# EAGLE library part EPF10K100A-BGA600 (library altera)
EPF10K100 FLEX 10K family
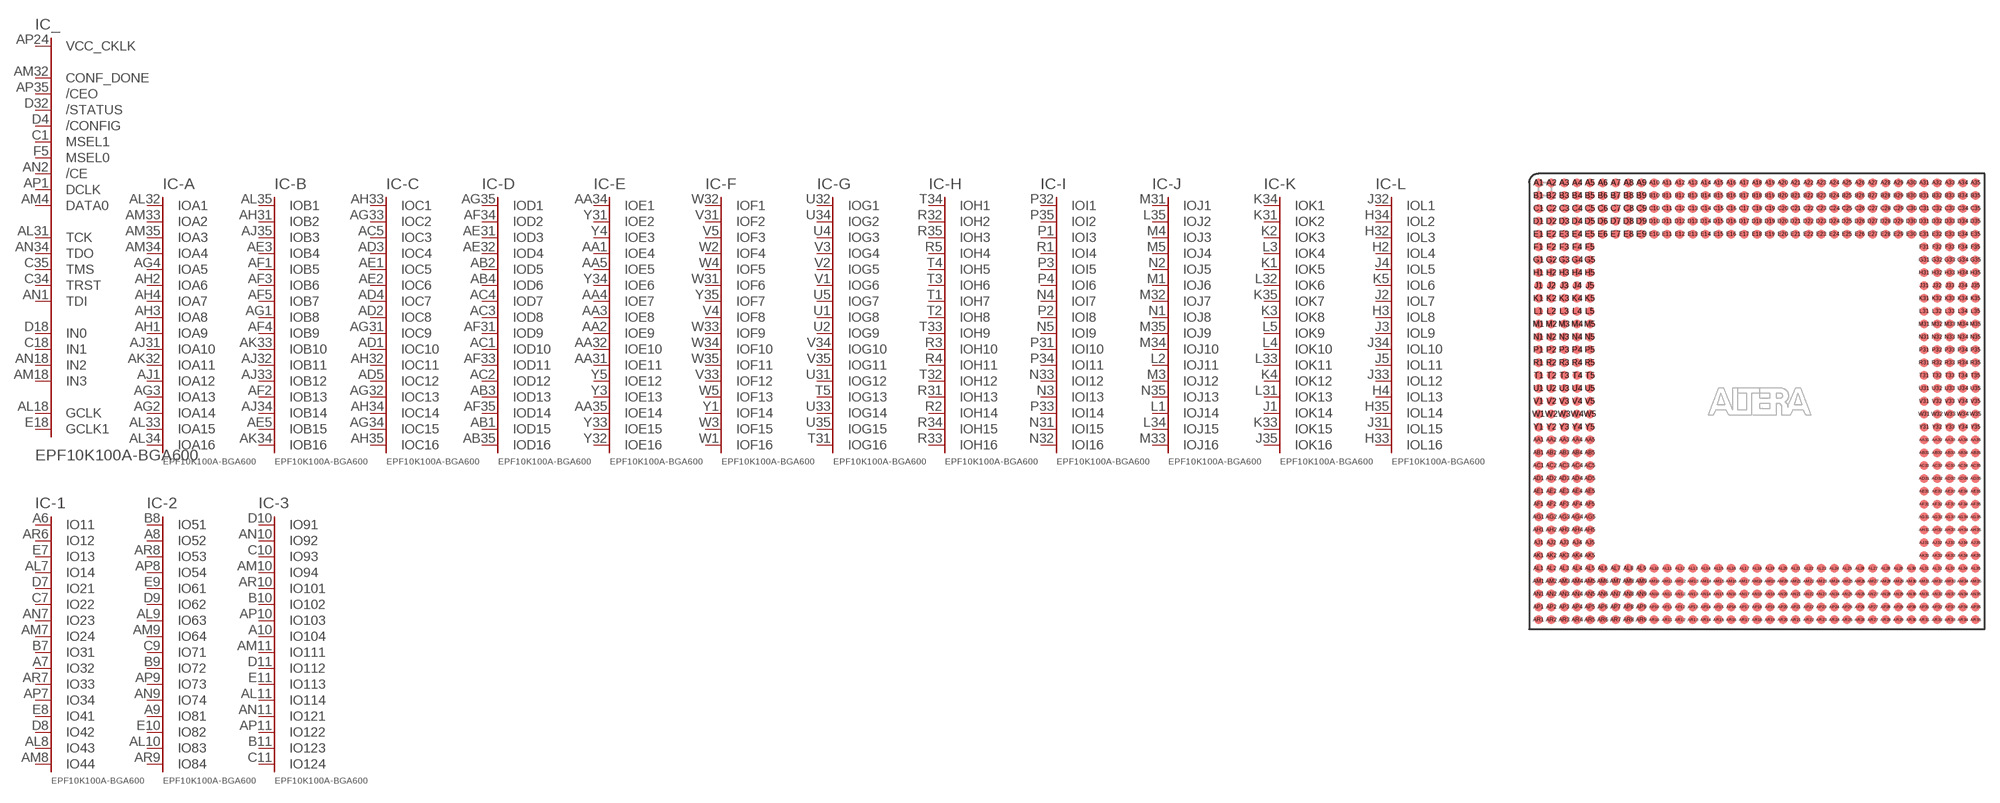
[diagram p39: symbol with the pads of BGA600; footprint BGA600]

Designator prefix IC; gates _=100B600C -A=A16 -B=B16 -C=C16 -D=D16 -E=E16 -F=F16 -G=G16 -H=H16 -I=I16 -J=J16 -K=K16 -L=L16 -1=IO44 -2=IO84 -3=IO124 -4=IO164 -5=IO204 -6=IO244 -7=IO284 -8=IO324 -9=IO364 -10=IO404 -11=IO444 -12=IO484 -13=IO524 G1=GND G2=GND G3=GND G4=GND G5=GND G6=GND G7=GND G8=GND G9=GND G10=GND G11=GND G12=GND G13=GND G14=GND G15=GND G16=GND G17=GND G18=GND G19=GND G20=GND G21=GND G22=GND G23=GND G24=GND G25=GND G26=GND G27=GND G28=GND G29=GND G30=GND G31=GND G32=GND G33=GND G34=GND G35=GND G36=GND G37=GND G38=GND G39=GND G40=GND G41=GND G42=GND G43=GND G44=GND G45=GND G46=GND G47=GND G48=GND G49=GND G50=GND G51=GND G52=GND G53=GND G54=GND G55=GND G56=GND G57=GND G58=GND NC1=NC NC2=NC NC3=NC NC4=NC NC5=NC NC6=NC NC7=NC NC8=NC NC9=NC NC10=NC NC11=NC NC12=NC NC13=NC NC14=NC NC15=NC NC16=NC NC17=NC NC18=NC NC19=NC NC20=NC NC21=NC NC22=NC NC23=NC NC24=NC NC25=NC NC26=NC NC27=NC NC28=NC NC29=NC NC30=NC NC31=NC NC32=NC NC33=NC NC34=NC NC35=NC NC36=NC NC37=NC NC38=NC NC39=NC NC40=NC NC41=NC NC42=NC NC43=NC NC44=NC NC45=NC NC46=NC NC47=NC NC48=NC NC49=NC NC50=NC NC51=NC NC52=NC NC53=NC NC54=NC NC55=NC NC56=NC NC57=NC NC58=NC NC59=NC NC60=NC NC61=NC NC62=NC NC63=NC NC64=NC V1=VCCINT V2=VCCINT V3=VCCINT V4=VCCINT V5=VCCINT V6=VCCINT V7=VCCINT V8=VCCINT V9=VCCINT V10=VCCINT V11=VCCINT V12=VCCINT V13=VCCINT V14=VCCINT V15=VCCINT V16=VCCINT V17=VCCINT V18=VCCINT V19=VCCINT V20=VCCINT V21=VCCINT V22=VCCINT V23=VCCINT V24=VCCINT V25=VCCINT V26=VCCINT V27=VCCINT V28=VCCINT VO1=VCCIO VO2=VCCIO VO3=VCCIO VO4=VCCIO VO5=VCCIO VO6=VCCIO VO7=VCCIO VO8=VCCIO VO9=VCCIO VO10=VCCIO VO11=VCCIO VO12=VCCIO VO13=VCCIO VO14=VCCIO VO15=VCCIO VO16=VCCIO VO17=VCCIO VO18=VCCIO VO19=VCCIO VO20=VCCIO VO21=VCCIO VO22=VCCIO VO23=VCCIO VO24=VCCIO VO25=VCCIO VO26=VCCIO VO27=VCCIO VO28=VCCIO VO29=VCCIO

## EPF10K100A-BGA600 (MPN: EPF10K100ABC600-1; OC_FARNELL: unknown; OC_NEWARK: 51R8783)  [BGA600]
A1  G30:GND  pwr
A2  G31:GND  pwr
A3  G32:GND  pwr
A4  G33:GND  pwr
A5  G34:GND  pwr
A6  -1:IO11
A7  -1:IO32
A8  -2:IO52
A9  -2:IO81
A10  -3:IO104
A11  V12:VCC  pwr
A12  -4:IO144
A13  -5:IO173
A14  -5:IO191
A15  -6:IO211
A16  -6:IO243
A17  -7:IO264
A18  G35:GND  pwr
A19  V13:VCC  pwr
A20  VO15:VCCIO  pwr
A21  -8:IO313
A22  -9:IO331
A23  -9:IO361
A24  -10:IO382
A25  -10:IO394
A26  -11:IO421
A27  VO16:VCCIO  pwr
A28  -12:IO472
A29  -13:IO492
A30  -13:IO523
A31  G36:GND  pwr
A32  G37:GND  pwr
A33  G38:GND  pwr
A34  G39:GND  pwr
A35  G40:GND  pwr
AA1  -E:IOE4
AA2  -E:IOE9
AA3  -E:IOE8
AA4  -E:IOE7
AA5  -E:IOE5
AA31  -E:IOE11
AA32  -E:IOE10
AA33  V1:VCC  pwr
AA34  -E:IOE1
AA35  -E:IOE14
AB1  -D:IOD15
AB2  -D:IOD5
AB3  -D:IOD13
AB4  -D:IOD6
AB5  V2:VCC  pwr
AB31  NC1:NC  nc
AB32  NC2:NC  nc
AB33  NC3:NC  nc
AB34  NC4:NC  nc
AB35  -D:IOD16
AC1  -D:IOD10
AC2  -D:IOD12
AC3  -D:IOD8
AC4  -D:IOD7
AC5  -C:IOC3
AC31  NC5:NC  nc
AC32  NC6:NC  nc
AC33  NC7:NC  nc
AC34  NC8:NC  nc
AC35  NC9:NC  nc
AD1  -C:IOC10
AD2  -C:IOC8
AD3  -C:IOC4
AD4  -C:IOC7
AD5  -C:IOC12
AD31  NC10:NC  nc
AD32  NC11:NC  nc
AD33  NC12:NC  nc
AD34  NC13:NC  nc
AD35  V3:VCC  pwr
AE1  -C:IOC5
AE2  -C:IOC6
AE3  -B:IOB4
AE4  V4:VCC  pwr
AE5  -B:IOB15
AE31  -D:IOD3
AE32  -D:IOD4
AE33  NC14:NC  nc
AE34  NC15:NC  nc
AE35  NC16:NC  nc
AF1  -B:IOB5
AF2  -B:IOB13
AF3  -B:IOB6
AF4  -B:IOB9
AF5  -B:IOB7
AF31  -D:IOD9
AF32  V5:VCC  pwr
AF33  -D:IOD11
AF34  -D:IOD2
AF35  -D:IOD14
AG1  -B:IOB8
AG2  -A:IOA14
AG3  -A:IOA13
AG4  -A:IOA5
AG5  V6:VCC  pwr
AG31  -C:IOC9
AG32  -C:IOC13
AG33  -C:IOC2
AG34  -C:IOC15
AG35  -D:IOD1
AH1  -A:IOA9
AH2  -A:IOA6
AH3  -A:IOA8
AH4  -A:IOA7
AH5  NC17:NC  nc
AH31  -B:IOB2
AH32  -C:IOC11
AH33  -C:IOC1
AH34  -C:IOC14
AH35  -C:IOC16
AJ1  -A:IOA12
AJ2  NC18:NC  nc
AJ3  NC19:NC  nc
AJ4  NC20:NC  nc
AJ5  NC21:NC  nc
AJ31  -A:IOA10
AJ32  -B:IOB11
AJ33  -B:IOB12
AJ34  -B:IOB14
AJ35  -B:IOB3
AK1  NC22:NC  nc
AK2  NC23:NC  nc
AK3  NC24:NC  nc
AK4  NC25:NC  nc
AK5  NC26:NC  nc
AK31  V7:VCC  pwr
AK32  -A:IOA11
AK33  -B:IOB10
AK34  -B:IOB16
AK35  V8:VCC  pwr
AL1  NC27:NC  nc
AL2  NC28:NC  nc
AL3  V9:VCC  pwr
AL4  NC29:NC  nc
AL5  VO1:VCCIO  pwr
AL6  G1:GND  pwr
AL7  -1:IO14
AL8  -1:IO43
AL9  -2:IO63
AL10  -2:IO83
AL11  -3:IO114
AL12  VO2:VCCIO  pwr
AL13  -4:IO154
AL14  -5:IO171
AL15  -5:IO204
AL16  -6:IO221
AL17  -6:IO242
AL18  _:GCLK  in
AL19  -8:IO292
AL20  -8:IO312
AL21  -9:IO343
AL22  -9:IO364
AL23  -10:IO381
AL24  -11:IO411
AL25  -11:IO434
AL26  -12:IO454
AL27  -12:IO471
AL28  -13:IO501
AL29  -13:IO522
AL30  G2:GND  pwr
AL31  _:TCK
AL32  -A:IOA1
AL33  -A:IOA15
AL34  -A:IOA16
AL35  -B:IOB1
AM1  NC30:NC  nc
AM2  NC31:NC  nc
AM3  NC32:NC  nc
AM4  _:DATA0  in
AM5  VO3:VCCIO  pwr
AM6  G3:GND  pwr
AM7  -1:IO24
AM8  -1:IO44
AM9  -2:IO64
AM10  -3:IO94
AM11  -3:IO111
AM12  -4:IO134
AM13  -4:IO152
AM14  -5:IO184
AM15  -5:IO201
AM16  -6:IO222
AM17  -7:IO253
AM18  _:IN3  in
AM19  VO4:VCCIO  pwr
AM20  -8:IO314
AM21  -9:IO333
AM22  -9:IO363
AM23  -10:IO384
AM24  -10:IO403
AM25  -11:IO423
AM26  VO5:VCCIO  pwr
AM27  -12:IO474
AM28  -13:IO491
AM29  -13:IO524
AM30  G4:GND  pwr
AM31  VO6:VCCIO  pwr
AM32  _:CONF_DONE  in
AM33  -A:IOA2
AM34  -A:IOA4
AM35  -A:IOA3
AN1  _:TDI
AN2  _:/CE  in
AN3  VO7:VCCIO  pwr
AN4  VO8:VCCIO  pwr
AN5  G5:GND  pwr
AN6  G6:GND  pwr
AN7  -1:IO23
AN8  VO9:VCCIO  pwr
AN9  -2:IO74
AN10  -3:IO92
AN11  -3:IO121
AN12  -4:IO132
AN13  -4:IO164
AN14  -5:IO182
AN15  VO10:VCCIO  pwr
AN16  -6:IO234
AN17  -7:IO252
AN18  _:IN2  in
AN19  -7:IO284
AN20  -8:IO302
AN21  -9:IO334
AN22  -9:IO353
AN23  -10:IO371
AN24  -10:IO391
AN25  -11:IO424
AN26  -11:IO441
AN27  -12:IO461
AN28  -13:IO494
AN29  -13:IO512
AN30  G7:GND  pwr
AN31  G8:GND  pwr
AN32  VO11:VCCIO  pwr
AN33  VO12:VCCIO  pwr
AN34  _:TDO
AN35  G9:GND  pwr
AP1  _:DCLK  in
AP2  G10:GND  pwr
AP3  G11:GND  pwr
AP4  G12:GND  pwr
AP5  G13:GND  pwr
AP6  G14:GND  pwr
AP7  -1:IO34
AP8  -2:IO54
AP9  -2:IO73
AP10  -3:IO103
AP11  -3:IO122
AP12  -4:IO142
AP13  -4:IO162
AP14  -5:IO194
AP15  -6:IO214
AP16  -6:IO232
AP17  -7:IO263
AP18  -7:IO274
AP19  -7:IO282
AP20  -8:IO304
AP21  -8:IO323
AP22  -9:IO354
AP23  -10:IO374
AP24  _:VCC_CKLK  pas
AP25  -11:IO412
AP26  -11:IO444
AP27  -12:IO464
AP28  -12:IO482
AP29  -13:IO514
AP30  G15:GND  pwr
AP31  G16:GND  pwr
AP32  G17:GND  pwr
AP33  G18:GND  pwr
AP34  VO13:VCCIO  pwr
AP35  _:/CEO  in
AR1  G19:GND  pwr
AR2  G20:GND  pwr
AR3  G21:GND  pwr
AR4  G22:GND  pwr
AR5  G23:GND  pwr
AR6  -1:IO12
AR7  -1:IO33
AR8  -2:IO53
AR9  -2:IO84
AR10  -3:IO101
AR11  V10:VCC  pwr
AR12  -4:IO143
AR13  -5:IO174
AR14  -5:IO192
AR15  -6:IO212
AR16  -6:IO244
AR17  -7:IO261
AR18  V11:VCC  pwr
AR19  -7:IO272
AR20  -8:IO294
AR21  -8:IO324
AR22  -9:IO344
AR23  VO14:VCCIO  pwr
AR24  -10:IO393
AR25  -10:IO404
AR26  -11:IO432
AR27  -12:IO452
AR28  -12:IO484
AR29  -13:IO502
AR30  G24:GND  pwr
AR31  G25:GND  pwr
AR32  G26:GND  pwr
AR33  G27:GND  pwr
AR34  G28:GND  pwr
AR35  G29:GND  pwr
B1  V14:VCC  pwr
B2  G41:GND  pwr
B3  G42:GND  pwr
B4  G43:GND  pwr
B5  G44:GND  pwr
B6  G45:GND  pwr
B7  -1:IO31
B8  -2:IO51
B9  -2:IO72
B10  -3:IO102
B11  -3:IO123
B12  -4:IO141
B13  -4:IO163
B14  -5:IO193
B15  -6:IO213
B16  -6:IO231
B17  -7:IO262
B18  V15:VCC  pwr
B19  -7:IO273
B20  -8:IO293
B21  -8:IO311
B22  -9:IO342
B23  -9:IO362
B24  -10:IO383
B25  -10:IO402
B26  -11:IO433
B27  -12:IO453
B28  -12:IO473
B29  -13:IO503
B30  -13:IO521
B31  G46:GND  pwr
B32  G47:GND  pwr
B33  G48:GND  pwr
B34  G49:GND  pwr
B35  G50:GND  pwr
C1  _:MSEL1  in
C2  VO17:VCCIO  pwr
C3  VO18:VCCIO  pwr
C4  VO19:VCCIO  pwr
C5  G51:GND  pwr
C6  G52:GND  pwr
C7  -1:IO22
C8  VO20:VCCIO  pwr
C9  -2:IO71
C10  -3:IO93
C11  -3:IO124
C12  -4:IO133
C13  -4:IO161
C14  -5:IO181
C15  VO21:VCCIO  pwr
C16  -6:IO233
C17  -7:IO251
C18  _:IN1  in
C19  -7:IO271
C20  -8:IO291
C21  -8:IO322
C22  -9:IO341
C23  VO22:VCCIO  pwr
C24  -10:IO392
C25  -11:IO413
C26  -11:IO431
C27  -12:IO451
C28  -12:IO483
C29  -13:IO504
C30  G53:GND  pwr
C31  G54:GND  pwr
C32  VO23:VCCIO  pwr
C33  VO24:VCCIO  pwr
C34  _:TRST
C35  _:TMS
D1  NC33:NC  nc
D2  NC34:NC  nc
D3  NC35:NC  nc
D4  _:/CONFIG  in
D5  VO25:VCCIO  pwr
D6  G55:GND  pwr
D7  -1:IO21
D8  -1:IO42
D9  -2:IO62
D10  -3:IO91
D11  -3:IO112
D12  -4:IO131
D13  -4:IO153
D14  -5:IO183
D15  -5:IO202
D16  -6:IO223
D17  -7:IO254
D18  _:IN0  in
D19  -7:IO283
D20  -8:IO303
D21  -8:IO321
D22  -9:IO352
D23  -10:IO373
D24  V16:VCC  pwr
D25  -11:IO414
D26  -11:IO442
D27  -12:IO463
D28  -12:IO481
D29  -13:IO513
D30  G56:GND  pwr
D31  VO26:VCCIO  pwr
D32  _:/STATUS  in
D33  NC36:NC  nc
D34  NC37:NC  nc
D35  NC38:NC  nc
E1  NC39:NC  nc
E2  V17:VCC  pwr
E3  NC40:NC  nc
E4  NC41:NC  nc
E5  VO27:VCCIO  pwr
E6  G57:GND  pwr
E7  -1:IO13
E8  -1:IO41
E9  -2:IO61
E10  -2:IO82
E11  -3:IO113
E12  VO28:VCCIO  pwr
E13  -4:IO151
E14  -5:IO172
E15  -5:IO203
E16  -6:IO224
E17  -6:IO241
E18  _:GCLK1  in
E19  -7:IO281
E20  -8:IO301
E21  -9:IO332
E22  -9:IO351
E23  -10:IO372
E24  -10:IO401
E25  -11:IO422
E26  -11:IO443
E27  -12:IO462
E28  -13:IO493
E29  -13:IO511
E30  G58:GND  pwr
E31  VO29:VCCIO  pwr
E32  NC42:NC  nc
E33  NC43:NC  nc
E34  NC44:NC  nc
E35  NC45:NC  nc
F1  NC46:NC  nc
F2  NC47:NC  nc
F3  NC48:NC  nc
F4  NC49:NC  nc
F5  _:MSEL0  in
F31  V18:VCC  pwr
F32  NC50:NC  nc
F33  NC51:NC  nc
F34  NC52:NC  nc
F35  V19:VCC  pwr
G1  NC53:NC  nc
G2  NC54:NC  nc
G3  NC55:NC  nc
G4  NC56:NC  nc
G5  NC57:NC  nc
G31  NC58:NC  nc
G32  NC59:NC  nc
G33  NC60:NC  nc
G34  NC61:NC  nc
G35  NC62:NC  nc
H1  V20:VCC  pwr
H2  -L:IOL4
H3  -L:IOL8
H4  -L:IOL13
H5  NC63:NC  nc
H31  NC64:NC  nc
H32  -L:IOL3
H33  -L:IOL16
H34  -L:IOL2
H35  -L:IOL14
J1  -K:IOK14
J2  -L:IOL7
J3  -L:IOL9
J4  -L:IOL5
J5  -L:IOL11
J31  -L:IOL15
J32  -L:IOL1
J33  -L:IOL12
J34  -L:IOL10
J35  -K:IOK16
K1  -K:IOK5
K2  -K:IOK3
K3  -K:IOK8
K4  -K:IOK12
K5  -L:IOL6
K31  -K:IOK2
K32  V21:VCC  pwr
K33  -K:IOK15
K34  -K:IOK1
K35  -K:IOK7
L1  -J:IOJ14
L2  -J:IOJ11
L3  -K:IOK4
L4  -K:IOK10
L5  -K:IOK9
L31  -K:IOK13
L32  -K:IOK6
L33  -K:IOK11
L34  -J:IOJ15
L35  -J:IOJ2
M1  -J:IOJ6
M2  V22:VCC  pwr
M3  -J:IOJ12
M4  -J:IOJ3
M5  -J:IOJ4
M31  -J:IOJ1
M32  -J:IOJ7
M33  -J:IOJ16
M34  -J:IOJ10
M35  -J:IOJ9
N1  -J:IOJ8
N2  -J:IOJ5
N3  -I:IOI13
N4  -I:IOI7
N5  -I:IOI9
N31  -I:IOI15
N32  -I:IOI16
N33  -I:IOI12
N34  V23:VCC  pwr
N35  -J:IOJ13
P1  -I:IOI3
P2  -I:IOI8
P3  -I:IOI5
P4  -I:IOI6
P5  V24:VCC  pwr
P31  -I:IOI10
P32  -I:IOI1
P33  -I:IOI14
P34  -I:IOI11
P35  -I:IOI2
R1  -I:IOI4
R2  -H:IOH14
R3  -H:IOH10
R4  -H:IOH11
R5  -H:IOH4
R31  -H:IOH13
R32  -H:IOH2
R33  -H:IOH16
R34  -H:IOH15
R35  -H:IOH3
T1  -H:IOH7
T2  -H:IOH8
T3  -H:IOH6
T4  -H:IOH5
T5  -G:IOG13
T31  -G:IOG16
T32  -H:IOH12
T33  -H:IOH9
T34  -H:IOH1
T35  V25:VCC  pwr
U1  -G:IOG8
U2  -G:IOG9
U3  V26:VCC  pwr
U4  -G:IOG3
U5  -G:IOG7
U31  -G:IOG12
U32  -G:IOG1
U33  -G:IOG14
U34  -G:IOG2
U35  -G:IOG15
V1  -G:IOG6
V2  -G:IOG5
V3  -G:IOG4
V4  -F:IOF8
V5  -F:IOF3
V31  -F:IOF2
V32  V27:VCC  pwr
V33  -F:IOF12
V34  -G:IOG10
V35  -G:IOG11
W1  -F:IOF16
W2  -F:IOF4
W3  -F:IOF15
W4  -F:IOF5
W5  -F:IOF13
W31  -F:IOF6
W32  -F:IOF1
W33  -F:IOF9
W34  -F:IOF10
W35  -F:IOF11
Y1  -F:IOF14
Y2  V28:VCC  pwr
Y3  -E:IOE13
Y4  -E:IOE3
Y5  -E:IOE12
Y31  -E:IOE2
Y32  -E:IOE16
Y33  -E:IOE15
Y34  -E:IOE6
Y35  -F:IOF7

## Footprint BGA600 (pad centres in mm)
Ball Grid Array
smd 0.9 x 0.9: A1 -21.59,21.59; A2 -20.32,21.59; A3 -19.05,21.59; A4 -17.78,21.59; A5 -16.51,21.59; A6 -15.24,21.59; A7 -13.97,21.59; A8 -12.7,21.59; A9 -11.43,21.59; A10 -10.16,21.59; A11 -8.89,21.59; A12 -7.62,21.59; A13 -6.35,21.59; A14 -5.08,21.59; A15 -3.81,21.59; A16 -2.54,21.59; A17 -1.27,21.59; A18 0,21.59; A19 1.27,21.59; A20 2.54,21.59; A21 3.81,21.59; A22 5.08,21.59; A23 6.35,21.59; A24 7.62,21.59; A25 8.89,21.59; A26 10.16,21.59; A27 11.43,21.59; A28 12.7,21.59; A29 13.97,21.59; A30 15.24,21.59; A31 16.51,21.59; A32 17.78,21.59; A33 19.05,21.59; A34 20.32,21.59; A35 21.59,21.59; AA1 -21.59,-3.81; AA2 -20.32,-3.81; AA3 -19.05,-3.81; AA4 -17.78,-3.81; AA5 -16.51,-3.81; AA31 16.51,-3.81; AA32 17.78,-3.81; AA33 19.05,-3.81; AA34 20.32,-3.81; AA35 21.59,-3.81; AB1 -21.59,-5.08; AB2 -20.32,-5.08; AB3 -19.05,-5.08; AB4 -17.78,-5.08; AB5 -16.51,-5.08; AB31 16.51,-5.08; AB32 17.78,-5.08; AB33 19.05,-5.08; AB34 20.32,-5.08; AB35 21.59,-5.08; AC1 -21.59,-6.35; AC2 -20.32,-6.35; AC3 -19.05,-6.35; AC4 -17.78,-6.35; AC5 -16.51,-6.35; AC31 16.51,-6.35; AC32 17.78,-6.35; AC33 19.05,-6.35; AC34 20.32,-6.35; AC35 21.59,-6.35; AD1 -21.59,-7.62; AD2 -20.32,-7.62; AD3 -19.05,-7.62; AD4 -17.78,-7.62; AD5 -16.51,-7.62; AD31 16.51,-7.62; AD32 17.78,-7.62; AD33 19.05,-7.62; AD34 20.32,-7.62; AD35 21.59,-7.62; AE1 -21.59,-8.89; AE2 -20.32,-8.89; AE3 -19.05,-8.89; AE4 -17.78,-8.89; AE5 -16.51,-8.89; AE31 16.51,-8.89; AE32 17.78,-8.89; AE33 19.05,-8.89; AE34 20.32,-8.89; AE35 21.59,-8.89; AF1 -21.59,-10.16; AF2 -20.32,-10.16; AF3 -19.05,-10.16; AF4 -17.78,-10.16; AF5 -16.51,-10.16; AF31 16.51,-10.16; AF32 17.78,-10.16; AF33 19.05,-10.16; AF34 20.32,-10.16; AF35 21.59,-10.16; AG1 -21.59,-11.43; AG2 -20.32,-11.43; AG3 -19.05,-11.43; AG4 -17.78,-11.43; AG5 -16.51,-11.43; AG31 16.51,-11.43; AG32 17.78,-11.43; AG33 19.05,-11.43; AG34 20.32,-11.43; AG35 21.59,-11.43; AH1 -21.59,-12.7; AH2 -20.32,-12.7; AH3 -19.05,-12.7; AH4 -17.78,-12.7; AH5 -16.51,-12.7; AH31 16.51,-12.7; AH32 17.78,-12.7; AH33 19.05,-12.7; AH34 20.32,-12.7; AH35 21.59,-12.7; AJ1 -21.59,-13.97; AJ2 -20.32,-13.97; AJ3 -19.05,-13.97; AJ4 -17.78,-13.97; AJ5 -16.51,-13.97; AJ31 16.51,-13.97; AJ32 17.78,-13.97; AJ33 19.05,-13.97; AJ34 20.32,-13.97; AJ35 21.59,-13.97; AK1 -21.59,-15.24; AK2 -20.32,-15.24; AK3 -19.05,-15.24; AK4 -17.78,-15.24; AK5 -16.51,-15.24; AK31 16.51,-15.24; AK32 17.78,-15.24; AK33 19.05,-15.24; AK34 20.32,-15.24; AK35 21.59,-15.24; AL1 -21.59,-16.51; AL2 -20.32,-16.51; AL3 -19.05,-16.51; AL4 -17.78,-16.51; AL5 -16.51,-16.51; AL6 -15.24,-16.51; AL7 -13.97,-16.51; AL8 -12.7,-16.51; AL9 -11.43,-16.51; AL10 -10.16,-16.51; AL11 -8.89,-16.51; AL12 -7.62,-16.51; AL13 -6.35,-16.51; AL14 -5.08,-16.51; AL15 -3.81,-16.51; AL16 -2.54,-16.51; AL17 -1.27,-16.51; AL18 0,-16.51; AL19 1.27,-16.51; AL20 2.54,-16.51; AL21 3.81,-16.51; AL22 5.08,-16.51; AL23 6.35,-16.51; AL24 7.62,-16.51; AL25 8.89,-16.51; AL26 10.16,-16.51; AL27 11.43,-16.51; AL28 12.7,-16.51; AL29 13.97,-16.51; AL30 15.24,-16.51; AL31 16.51,-16.51; AL32 17.78,-16.51; AL33 19.05,-16.51; AL34 20.32,-16.51; AL35 21.59,-16.51; AM1 -21.59,-17.78; AM2 -20.32,-17.78; AM3 -19.05,-17.78; AM4 -17.78,-17.78; AM5 -16.51,-17.78; AM6 -15.24,-17.78; AM7 -13.97,-17.78; AM8 -12.7,-17.78; AM9 -11.43,-17.78; AM10 -10.16,-17.78; AM11 -8.89,-17.78; AM12 -7.62,-17.78; AM13 -6.35,-17.78; AM14 -5.08,-17.78; AM15 -3.81,-17.78; AM16 -2.54,-17.78; AM17 -1.27,-17.78; AM18 0,-17.78; AM19 1.27,-17.78; AM20 2.54,-17.78; AM21 3.81,-17.78; AM22 5.08,-17.78; AM23 6.35,-17.78; AM24 7.62,-17.78; AM25 8.89,-17.78; AM26 10.16,-17.78; AM27 11.43,-17.78; AM28 12.7,-17.78; AM29 13.97,-17.78; AM30 15.24,-17.78; AM31 16.51,-17.78; AM32 17.78,-17.78; AM33 19.05,-17.78; AM34 20.32,-17.78; AM35 21.59,-17.78; AN1 -21.59,-19.05; AN2 -20.32,-19.05; AN3 -19.05,-19.05; AN4 -17.78,-19.05; AN5 -16.51,-19.05; AN6 -15.24,-19.05; AN7 -13.97,-19.05; AN8 -12.7,-19.05; AN9 -11.43,-19.05; AN10 -10.16,-19.05; AN11 -8.89,-19.05; AN12 -7.62,-19.05; AN13 -6.35,-19.05; AN14 -5.08,-19.05; AN15 -3.81,-19.05; AN16 -2.54,-19.05; AN17 -1.27,-19.05; AN18 0,-19.05; AN19 1.27,-19.05; AN20 2.54,-19.05; AN21 3.81,-19.05; AN22 5.08,-19.05; AN23 6.35,-19.05; AN24 7.62,-19.05; AN25 8.89,-19.05; AN26 10.16,-19.05; AN27 11.43,-19.05; AN28 12.7,-19.05; AN29 13.97,-19.05; AN30 15.24,-19.05; AN31 16.51,-19.05; AN32 17.78,-19.05; AN33 19.05,-19.05; AN34 20.32,-19.05; AN35 21.59,-19.05; AP1 -21.59,-20.32; AP2 -20.32,-20.32; AP3 -19.05,-20.32; AP4 -17.78,-20.32; AP5 -16.51,-20.32; AP6 -15.24,-20.32; AP7 -13.97,-20.32; AP8 -12.7,-20.32; AP9 -11.43,-20.32; AP10 -10.16,-20.32; AP11 -8.89,-20.32; AP12 -7.62,-20.32; AP13 -6.35,-20.32; AP14 -5.08,-20.32; AP15 -3.81,-20.32; AP16 -2.54,-20.32; AP17 -1.27,-20.32; AP18 0,-20.32; AP19 1.27,-20.32; AP20 2.54,-20.32; AP21 3.81,-20.32; AP22 5.08,-20.32; AP23 6.35,-20.32; AP24 7.62,-20.32; AP25 8.89,-20.32; AP26 10.16,-20.32; AP27 11.43,-20.32; AP28 12.7,-20.32; AP29 13.97,-20.32; AP30 15.24,-20.32; AP31 16.51,-20.32; AP32 17.78,-20.32; AP33 19.05,-20.32; AP34 20.32,-20.32; AP35 21.59,-20.32; AR1 -21.59,-21.59; AR2 -20.32,-21.59; AR3 -19.05,-21.59; AR4 -17.78,-21.59; AR5 -16.51,-21.59; AR6 -15.24,-21.59; AR7 -13.97,-21.59; AR8 -12.7,-21.59; AR9 -11.43,-21.59; AR10 -10.16,-21.59; AR11 -8.89,-21.59; AR12 -7.62,-21.59; AR13 -6.35,-21.59; AR14 -5.08,-21.59; AR15 -3.81,-21.59; AR16 -2.54,-21.59; AR17 -1.27,-21.59; AR18 0,-21.59; AR19 1.27,-21.59; AR20 2.54,-21.59; AR21 3.81,-21.59; AR22 5.08,-21.59; AR23 6.35,-21.59; AR24 7.62,-21.59; AR25 8.89,-21.59; AR26 10.16,-21.59; AR27 11.43,-21.59; AR28 12.7,-21.59; AR29 13.97,-21.59; AR30 15.24,-21.59; AR31 16.51,-21.59; AR32 17.78,-21.59; AR33 19.05,-21.59; AR34 20.32,-21.59; AR35 21.59,-21.59; B1 -21.59,20.32; B2 -20.32,20.32; B3 -19.05,20.32; B4 -17.78,20.32; B5 -16.51,20.32; B6 -15.24,20.32; B7 -13.97,20.32; B8 -12.7,20.32; B9 -11.43,20.32; B10 -10.16,20.32; B11 -8.89,20.32; B12 -7.62,20.32; B13 -6.35,20.32; B14 -5.08,20.32; B15 -3.81,20.32; B16 -2.54,20.32; B17 -1.27,20.32; B18 0,20.32; B19 1.27,20.32; B20 2.54,20.32; B21 3.81,20.32; B22 5.08,20.32; B23 6.35,20.32; B24 7.62,20.32; B25 8.89,20.32; B26 10.16,20.32; B27 11.43,20.32; B28 12.7,20.32; B29 13.97,20.32; B30 15.24,20.32; B31 16.51,20.32; B32 17.78,20.32; B33 19.05,20.32; B34 20.32,20.32; B35 21.59,20.32; C1 -21.59,19.05; C2 -20.32,19.05; C3 -19.05,19.05; C4 -17.78,19.05; C5 -16.51,19.05; C6 -15.24,19.05; C7 -13.97,19.05; C8 -12.7,19.05; C9 -11.43,19.05; C10 -10.16,19.05; C11 -8.89,19.05; C12 -7.62,19.05; C13 -6.35,19.05; C14 -5.08,19.05; C15 -3.81,19.05; C16 -2.54,19.05; C17 -1.27,19.05; C18 0,19.05; C19 1.27,19.05; C20 2.54,19.05; C21 3.81,19.05; C22 5.08,19.05; C23 6.35,19.05; C24 7.62,19.05; C25 8.89,19.05; C26 10.16,19.05; C27 11.43,19.05; C28 12.7,19.05; C29 13.97,19.05; C30 15.24,19.05; C31 16.51,19.05; C32 17.78,19.05; C33 19.05,19.05; C34 20.32,19.05; C35 21.59,19.05; D1 -21.59,17.78; D2 -20.32,17.78; D3 -19.05,17.78; D4 -17.78,17.78; D5 -16.51,17.78; D6 -15.24,17.78; D7 -13.97,17.78; D8 -12.7,17.78; D9 -11.43,17.78; D10 -10.16,17.78; D11 -8.89,17.78; D12 -7.62,17.78; D13 -6.35,17.78; D14 -5.08,17.78; D15 -3.81,17.78; D16 -2.54,17.78; D17 -1.27,17.78; D18 0,17.78; D19 1.27,17.78; D20 2.54,17.78; D21 3.81,17.78; D22 5.08,17.78; D23 6.35,17.78; D24 7.62,17.78; D25 8.89,17.78; D26 10.16,17.78; D27 11.43,17.78; D28 12.7,17.78; D29 13.97,17.78; D30 15.24,17.78; D31 16.51,17.78; D32 17.78,17.78; D33 19.05,17.78; D34 20.32,17.78; D35 21.59,17.78; E1 -21.59,16.51; E2 -20.32,16.51; E3 -19.05,16.51; E4 -17.78,16.51; E5 -16.51,16.51; E6 -15.24,16.51; E7 -13.97,16.51; E8 -12.7,16.51; E9 -11.43,16.51; E10 -10.16,16.51; E11 -8.89,16.51; E12 -7.62,16.51; E13 -6.35,16.51; E14 -5.08,16.51; E15 -3.81,16.51; E16 -2.54,16.51; E17 -1.27,16.51; E18 0,16.51; E19 1.27,16.51; E20 2.54,16.51; E21 3.81,16.51; E22 5.08,16.51; E23 6.35,16.51; E24 7.62,16.51; E25 8.89,16.51; E26 10.16,16.51; E27 11.43,16.51; E28 12.7,16.51; E29 13.97,16.51; E30 15.24,16.51; E31 16.51,16.51; E32 17.78,16.51; E33 19.05,16.51; E34 20.32,16.51; E35 21.59,16.51; F1 -21.59,15.24; F2 -20.32,15.24; F3 -19.05,15.24; F4 -17.78,15.24; F5 -16.51,15.24; F31 16.51,15.24; F32 17.78,15.24; F33 19.05,15.24; F34 20.32,15.24; F35 21.59,15.24; G1 -21.59,13.97; G2 -20.32,13.97; G3 -19.05,13.97; G4 -17.78,13.97; G5 -16.51,13.97; G31 16.51,13.97; G32 17.78,13.97; G33 19.05,13.97; G34 20.32,13.97; G35 21.59,13.97; H1 -21.59,12.7; H2 -20.32,12.7; H3 -19.05,12.7; H4 -17.78,12.7; H5 -16.51,12.7; H31 16.51,12.7; H32 17.78,12.7; H33 19.05,12.7; H34 20.32,12.7; H35 21.59,12.7; J1 -21.59,11.43; J2 -20.32,11.43; J3 -19.05,11.43; J4 -17.78,11.43; J5 -16.51,11.43; J31 16.51,11.43; J32 17.78,11.43; J33 19.05,11.43; J34 20.32,11.43; J35 21.59,11.43; K1 -21.59,10.16; K2 -20.32,10.16; K3 -19.05,10.16; K4 -17.78,10.16; K5 -16.51,10.16; K31 16.51,10.16; K32 17.78,10.16; K33 19.05,10.16; K34 20.32,10.16; K35 21.59,10.16; L1 -21.59,8.89; L2 -20.32,8.89; L3 -19.05,8.89; L4 -17.78,8.89; L5 -16.51,8.89; L31 16.51,8.89; L32 17.78,8.89; L33 19.05,8.89; L34 20.32,8.89; L35 21.59,8.89; M1 -21.59,7.62; M2 -20.32,7.62; M3 -19.05,7.62; M4 -17.78,7.62; M5 -16.51,7.62; M31 16.51,7.62; M32 17.78,7.62; M33 19.05,7.62; M34 20.32,7.62; M35 21.59,7.62; N1 -21.59,6.35; N2 -20.32,6.35; N3 -19.05,6.35; N4 -17.78,6.35; N5 -16.51,6.35; N31 16.51,6.35; N32 17.78,6.35; N33 19.05,6.35; N34 20.32,6.35; N35 21.59,6.35; P1 -21.59,5.08; P2 -20.32,5.08; P3 -19.05,5.08; P4 -17.78,5.08; P5 -16.51,5.08; P31 16.51,5.08; P32 17.78,5.08; P33 19.05,5.08; P34 20.32,5.08; P35 21.59,5.08; R1 -21.59,3.81; R2 -20.32,3.81; R3 -19.05,3.81; R4 -17.78,3.81; R5 -16.51,3.81; R31 16.51,3.81; R32 17.78,3.81; R33 19.05,3.81; R34 20.32,3.81; R35 21.59,3.81; T1 -21.59,2.54; T2 -20.32,2.54; T3 -19.05,2.54; T4 -17.78,2.54; T5 -16.51,2.54; T31 16.51,2.54; T32 17.78,2.54; T33 19.05,2.54; T34 20.32,2.54; T35 21.59,2.54; U1 -21.59,1.27; U2 -20.32,1.27; U3 -19.05,1.27; U4 -17.78,1.27; U5 -16.51,1.27; U31 16.51,1.27; U32 17.78,1.27; U33 19.05,1.27; U34 20.32,1.27; U35 21.59,1.27; V1 -21.59,0; V2 -20.32,0; V3 -19.05,0; V4 -17.78,0; V5 -16.51,0; V31 16.51,0; V32 17.78,0; V33 19.05,0; V34 20.32,0; V35 21.59,0; W1 -21.59,-1.27; W2 -20.32,-1.27; W3 -19.05,-1.27; W4 -17.78,-1.27; W5 -16.51,-1.27; W31 16.51,-1.27; W32 17.78,-1.27; W33 19.05,-1.27; W34 20.32,-1.27; W35 21.59,-1.27; Y1 -21.59,-2.54; Y2 -20.32,-2.54; Y3 -19.05,-2.54; Y4 -17.78,-2.54; Y5 -16.51,-2.54; Y31 16.51,-2.54; Y32 17.78,-2.54; Y33 19.05,-2.54; Y34 20.32,-2.54; Y35 21.59,-2.54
